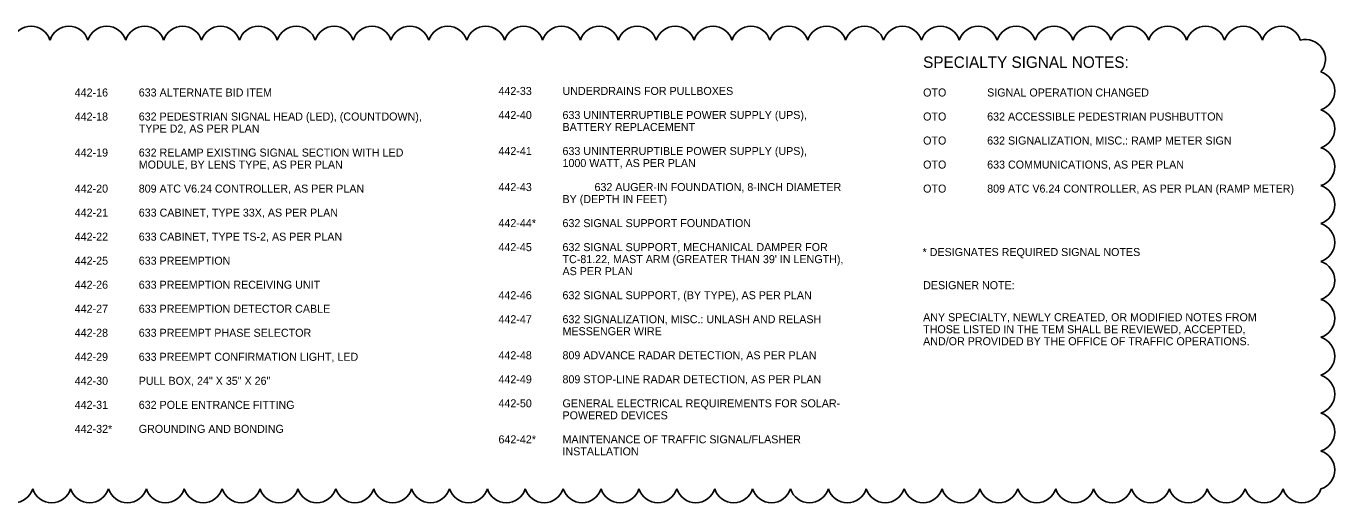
# Model space of a CAD drawing. Extents: x -16 to 109, y -28 to 34.
# Drawn here: x 10.32 to 33.21, y 25.22 to 33.55 of the extents above; entities that cross this region are included whole.
import ezdxf

# ---------------------------------------------------------------- set-up
doc = ezdxf.new("R2010")
doc.units = 0
doc.layers.add('SC_Scratch1', color=7, linetype='Continuous')

msp = doc.modelspace()

# ---------------------------------------------------------------- linework, layer by layer
at = {"layer": 'SC_Scratch1'}
for centre, start, end in [((10.406, 33.203), 17.5, 162.5), ((11.069, 33.203), 17.5, 162.5), ((11.732, 33.203), 17.5, 162.5), ((12.394, 33.203), 17.5, 162.5), ((13.057, 33.203), 17.5, 162.5), ((13.72, 33.203), 17.5, 162.5), ((14.383, 33.203), 17.5, 162.5), ((15.045, 33.203), 17.5, 162.5), ((15.708, 33.203), 17.5, 162.5), ((16.371, 33.203), 17.5, 162.5), ((17.033, 33.203), 17.5, 162.5), ((17.696, 33.203), 17.5, 162.5), ((18.359, 33.203), 17.5, 162.5), ((19.022, 33.203), 17.5, 162.5), ((19.684, 33.203), 17.5, 162.5), ((20.347, 33.203), 17.5, 162.5), ((21.01, 33.203), 17.5, 162.5), ((21.673, 33.203), 17.5, 162.5), ((22.335, 33.203), 17.5, 162.5), ((22.998, 33.203), 17.5, 162.5), ((23.661, 33.203), 17.5, 162.5), ((24.323, 33.203), 17.5, 162.5), ((24.986, 33.203), 17.5, 162.5), ((25.649, 33.203), 17.5, 162.5), ((26.312, 33.203), 17.5, 162.5), ((26.974, 33.203), 17.5, 162.5), ((27.637, 33.203), 17.5, 162.5), ((28.3, 33.203), 17.5, 162.5), ((28.963, 33.203), 17.5, 162.5), ((29.625, 33.203), 17.5, 162.5), ((30.288, 33.203), 17.5, 162.5), ((30.951, 33.203), 17.5, 162.5), ((31.613, 33.203), 17.5, 162.5), ((32.276, 33.203), 17.5, 162.5), ((32.7, 32.972), 320.4948, 105.4948), ((32.864, 32.42), 287.5, 72.5), ((32.864, 31.757), 287.5, 72.5), ((32.864, 31.095), 287.5, 72.5), ((32.864, 30.432), 287.5, 72.5), ((32.864, 29.769), 287.5, 72.5), ((32.864, 29.106), 287.5, 72.5), ((32.864, 28.444), 287.5, 72.5), ((32.864, 27.781), 287.5, 72.5), ((32.864, 27.118), 287.5, 72.5), ((32.864, 26.456), 287.5, 72.5), ((32.864, 25.793), 287.5, 72.5), ((10.104, 25.566), 197.5, 342.5), ((10.767, 25.566), 197.5, 342.5), ((11.43, 25.566), 197.5, 342.5), ((12.092, 25.566), 197.5, 342.5), ((12.755, 25.566), 197.5, 342.5), ((13.418, 25.566), 197.5, 342.5), ((14.081, 25.566), 197.5, 342.5), ((14.743, 25.566), 197.5, 342.5), ((15.406, 25.566), 197.5, 342.5), ((16.069, 25.566), 197.5, 342.5), ((16.732, 25.566), 197.5, 342.5), ((17.394, 25.566), 197.5, 342.5), ((18.057, 25.566), 197.5, 342.5), ((18.72, 25.566), 197.5, 342.5), ((19.382, 25.566), 197.5, 342.5), ((20.045, 25.566), 197.5, 342.5), ((20.708, 25.566), 197.5, 342.5), ((21.371, 25.566), 197.5, 342.5), ((22.033, 25.566), 197.5, 342.5), ((22.696, 25.566), 197.5, 342.5), ((23.359, 25.566), 197.5, 342.5), ((24.021, 25.566), 197.5, 342.5), ((24.684, 25.566), 197.5, 342.5), ((25.347, 25.566), 197.5, 342.5), ((26.01, 25.566), 197.5, 342.5), ((26.672, 25.566), 197.5, 342.5), ((27.335, 25.566), 197.5, 342.5), ((27.998, 25.566), 197.5, 342.5), ((28.661, 25.566), 197.5, 342.5), ((29.323, 25.566), 197.5, 342.5), ((29.986, 25.566), 197.5, 342.5), ((30.649, 25.566), 197.5, 342.5), ((31.311, 25.566), 197.5, 342.5), ((31.974, 25.566), 197.5, 342.5), ((32.637, 25.566), 197.5, 342.5)]:
    msp.add_arc(centre, 0.347, start, end, dxfattribs=at)

# ---------------------------------------------------------------- texts
for s, height, p in [('SPECIALTY SIGNAL NOTES:', 0.2, (26.01, 32.821)), ('442-16 ', 0.14, (11.17, 32.321)), ('633 ALTERNATE BID ITEM', 0.14, (12.29, 32.321)), ('442-33 ', 0.14, (18.582, 32.348)), ('UNDERDRAINS FOR PULLBOXES', 0.14, (19.702, 32.348)), ('OTO', 0.14, (26.01, 32.321)), ('SIGNAL OPERATION CHANGED', 0.14, (27.13, 32.321)), ('632 PEDESTRIAN SIGNAL HEAD (LED), (COUNTDOWN), ', 0.14, (12.29, 31.901)), ('442-40 ', 0.14, (18.582, 31.928)), ('633 UNINTERRUPTIBLE POWER SUPPLY (UPS), ', 0.14, (19.702, 31.928)), ('442-18 ', 0.14, (11.17, 31.901)), ('TYPE D2, AS PER PLAN', 0.14, (12.29, 31.691)), ('BATTERY REPLACEMENT', 0.14, (19.702, 31.718)), ('OTO', 0.14, (26.01, 31.901)), ('632 ACCESSIBLE PEDESTRIAN PUSHBUTTON', 0.14, (27.13, 31.901)), ('OTO', 0.14, (26.01, 31.481)), ('632 SIGNALIZATION, MISC.: RAMP METER SIGN', 0.14, (27.13, 31.481)), ('442-19 ', 0.14, (11.17, 31.271)), ('632 RELAMP EXISTING SIGNAL SECTION WITH LED ', 0.14, (12.29, 31.271)), ('442-41 ', 0.14, (18.582, 31.298)), ('633 UNINTERRUPTIBLE POWER SUPPLY (UPS), ', 0.14, (19.702, 31.298)), ('MODULE, BY LENS TYPE, AS PER PLAN', 0.14, (12.29, 31.061)), ('1000 WATT, AS PER PLAN', 0.14, (19.702, 31.088)), ('OTO', 0.14, (26.01, 31.061)), ('633 COMMUNICATIONS, AS PER PLAN', 0.14, (27.13, 31.061)), ('442-20 ', 0.14, (11.17, 30.641)), ('809 ATC V6.24 CONTROLLER, AS PER PLAN', 0.14, (12.29, 30.641)), ('442-43', 0.14, (18.582, 30.668)), ('632 AUGER-IN FOUNDATION, 8-INCH DIAMETER', 0.14, (20.262, 30.668)), ('OTO', 0.14, (26.01, 30.641)), ('809 ATC V6.24 CONTROLLER, AS PER PLAN (RAMP METER)', 0.14, (27.13, 30.641)), ('BY (DEPTH IN FEET)', 0.14, (19.702, 30.458)), ('442-21 ', 0.14, (11.17, 30.221)), ('633 CABINET, TYPE 33X, AS PER PLAN', 0.14, (12.29, 30.221)), ('442-44* ', 0.14, (18.582, 30.038)), ('632 SIGNAL SUPPORT FOUNDATION', 0.14, (19.702, 30.038)), ('442-22 ', 0.14, (11.17, 29.801)), ('633 CABINET, TYPE TS-2, AS PER PLAN', 0.14, (12.29, 29.801)), ('442-45 ', 0.14, (18.582, 29.618)), ('632 SIGNAL SUPPORT, MECHANICAL DAMPER FOR ', 0.14, (19.702, 29.618)), ("TC-81.22, MAST ARM (GREATER THAN 39' IN LENGTH), ", 0.14, (19.702, 29.408)), ('* DESIGNATES REQUIRED SIGNAL NOTES', 0.14, (26, 29.532)), ('442-25 ', 0.14, (11.17, 29.381)), ('633 PREEMPTION', 0.14, (12.29, 29.381)), ('AS PER PLAN ', 0.14, (19.702, 29.198)), ('442-26 ', 0.14, (11.17, 28.961)), ('633 PREEMPTION RECEIVING UNIT', 0.14, (12.29, 28.961)), ('DESIGNER NOTE:', 0.14, (26.01, 28.953)), ('442-46 ', 0.14, (18.582, 28.778)), ('632 SIGNAL SUPPORT, (BY TYPE), AS PER PLAN', 0.14, (19.702, 28.778)), ('442-27 ', 0.14, (11.17, 28.541)), ('633 PREEMPTION DETECTOR CABLE', 0.14, (12.29, 28.541)), ('442-47 ', 0.14, (18.582, 28.358)), ('632 SIGNALIZATION, MISC.: UNLASH AND RELASH ', 0.14, (19.702, 28.358)), ('ANY SPECIALTY, NEWLY CREATED, OR MODIFIED NOTES FROM ', 0.14, (26.01, 28.393)), ('442-28 ', 0.14, (11.17, 28.121)), ('633 PREEMPT PHASE SELECTOR', 0.14, (12.29, 28.121)), ('MESSENGER WIRE', 0.14, (19.702, 28.148)), ('THOSE LISTED IN THE TEM SHALL BE REVIEWED, ACCEPTED, ', 0.14, (26.01, 28.183)), ('AND/OR PROVIDED BY THE OFFICE OF TRAFFIC OPERATIONS.', 0.14, (26.01, 27.973)), ('442-29 ', 0.14, (11.17, 27.701)), ('633 PREEMPT CONFIRMATION LIGHT, LED', 0.14, (12.29, 27.701)), ('442-48 ', 0.14, (18.582, 27.728)), ('809 ADVANCE RADAR DETECTION, AS PER PLAN', 0.14, (19.702, 27.728)), ('442-30 ', 0.14, (11.17, 27.281)), ('PULL BOX, 24" X 35" X 26"', 0.14, (12.29, 27.281)), ('442-49 ', 0.14, (18.582, 27.308)), ('809 STOP-LINE RADAR DETECTION, AS PER PLAN', 0.14, (19.702, 27.308)), ('442-50 ', 0.14, (18.582, 26.888)), ('GENERAL ELECTRICAL REQUIREMENTS FOR SOLAR-', 0.14, (19.702, 26.888)), ('442-31 ', 0.14, (11.17, 26.861)), ('632 POLE ENTRANCE FITTING', 0.14, (12.29, 26.861)), ('POWERED DEVICES', 0.14, (19.702, 26.678)), ('442-32*', 0.14, (11.17, 26.441)), ('GROUNDING AND BONDING', 0.14, (12.29, 26.441)), ('642-42* ', 0.14, (18.582, 26.258)), ('MAINTENANCE OF TRAFFIC SIGNAL/FLASHER', 0.14, (19.702, 26.258)), ('INSTALLATION', 0.14, (19.702, 26.048))]:
    msp.add_text(s, height=height, dxfattribs=at).set_placement(p)

doc.saveas('drawing.dxf')
